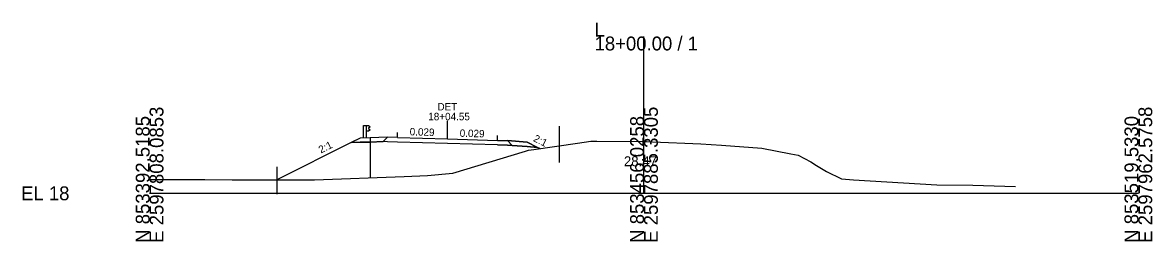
# Model space of a CAD drawing. Extents: x -26 to 1203, y -10 to 9526.
# Drawn here: x -25.7 to 202.8, y 7990.3 to 8034.4 of the extents above; entities that cross this region are included whole.
import ezdxf

# ---------------------------------------------------------------- set-up
doc = ezdxf.new("R2010")
doc.units = 0
for name, color, linetype in [('Exist Cross Section Cell', 7, 'Continuous'), ('Exist XS Center Line Elevation Label', 7, 'Continuous'), ('Exist XS Ground Line', 7, 'Continuous'), ('Prop XS Alignment Label', 7, 'Continuous'), ('Prop XS Earthwork Shape', 7, 'Continuous'), ('Prop XS EOT Tick Mark', 7, 'Continuous'), ('Prop XS Exc Vertical Line 1', 7, 'Continuous'), ('Prop XS Exc Vertical Line 2', 7, 'Continuous'), ('Prop XS Finish Grade', 7, 'Continuous'), ('Prop XS Finish Grade Earthwork', 7, 'Continuous'), ('Prop XS Finish Grade Paved Shoulder', 7, 'Continuous'), ('Prop XS Finish Grade Pavement', 7, 'Continuous'), ('Prop XS Guardrail', 7, 'Continuous'), ('Prop XS Pvmt Edge Slope', 7, 'Continuous'), ('Prop XS SE Text', 7, 'Continuous'), ('Prop XS Side Slope Text', 7, 'Continuous'), ('Prop XS Station Labels', 7, 'Continuous'), ('Prop XS Subgrade Earthwork', 7, 'Continuous'), ('Scratch_Level_1', 7, 'Continuous'), ('Scratch_Level_2', 7, 'Continuous')]:
    doc.layers.add(name, color=color, linetype=linetype)

msp = doc.modelspace()

# ---------------------------------------------------------------- linework, layer by layer
at = {"layer": 'Exist Cross Section Cell'}
for p, q in [((100, 8000), (100, 8031.63)), ((0, 8000), (100, 8000)), ((100, 8000), (200, 8000))]:
    msp.add_line(p, q, dxfattribs=at)
at = {"layer": 'Exist XS Ground Line'}
for p, q in [((77.75, 8008.84), (86.54, 8010.15)), ((86.54, 8010.15), (89.23, 8010.54)), ((89.23, 8010.54), (90.45, 8010.54)), ((90.45, 8010.54), (100, 8010.47)), ((100, 8010.47), (100.49, 8010.47)), ((100.49, 8010.47), (101.71, 8010.42)), ((101.71, 8010.42), (111.51, 8009.99)), ((61.31, 8004.06), (76.04, 8008.53)), ((76.04, 8008.53), (76.67, 8008.69)), ((76.67, 8008.69), (77.75, 8008.84)), ((111.51, 8009.99), (115.66, 8009.7)), ((115.66, 8009.7), (123.82, 8009.14)), ((123.82, 8009.14), (129.69, 8007.97)), ((129.69, 8007.97), (131.21, 8007.7)), ((131.21, 8007.7), (133.73, 8006.33)), ((133.73, 8006.33), (134.9, 8005.61)), ((134.9, 8005.61), (136.93, 8004.39)), ((33.33, 8002.71), (51.5, 8003.41)), ((51.5, 8003.41), (56.24, 8003.57)), ((56.24, 8003.57), (61.31, 8004.06)), ((136.93, 8004.39), (139.94, 8002.91)), ((0, 8002.82), (1.73, 8002.77)), ((1.73, 8002.77), (6.34, 8002.78)), ((6.34, 8002.78), (11.16, 8002.8)), ((11.16, 8002.8), (16.68, 8002.72)), ((16.68, 8002.72), (33.33, 8002.71)), ((139.94, 8002.91), (142.38, 8002.75)), ((142.38, 8002.75), (159.24, 8001.69)), ((159.24, 8001.69), (166.54, 8001.67)), ((166.54, 8001.67), (175.14, 8001.4))]:
    msp.add_line(p, q, dxfattribs=at)
at = {"layer": 'Prop XS Earthwork Shape'}
msp.add_lwpolyline([(60.25, 8010.06), (50.14, 8010.35), (48.14, 8010.41), (47.24, 8010.43), (44.59, 8010.35), (42.59, 8010.29), (40.75, 8010.23), (25.71, 8002.71), (33.33, 8002.71), (51.5, 8003.41), (56.24, 8003.57), (61.31, 8004.06), (76.04, 8008.53), (76.67, 8008.69), (77.75, 8008.84), (78.94, 8009.02), (78.44, 8009.27), (76.37, 8009.44), (73.31, 8009.68), (72.37, 8009.71), (70.37, 8009.77)], close=True, dxfattribs=at)
at = {"layer": 'Prop XS EOT Tick Mark'}
for p, q in [((50.14, 8011.27), (50.14, 8012.27)), ((70.37, 8010.68), (70.37, 8011.68))]:
    msp.add_line(p, q, dxfattribs=at)
at = {"layer": 'Prop XS Exc Vertical Line 1'}
msp.add_line((25.7, 8005.37), (25.7, 7999.8), dxfattribs=at)
at = {"layer": 'Prop XS Exc Vertical Line 2'}
msp.add_line((82.82, 8013.56), (82.82, 8006.22), dxfattribs=at)
at = {"layer": 'Prop XS Finish Grade'}
for p, q in [((42.59, 8011.15), (40.75, 8010.23)), ((44.59, 8011.21), (42.59, 8011.15)), ((48.14, 8011.32), (44.59, 8011.21)), ((72.37, 8010.63), (76.37, 8010.31)), ((76.37, 8010.31), (78.44, 8009.27))]:
    msp.add_line(p, q, dxfattribs=at)
at = {"layer": 'Prop XS Finish Grade Earthwork'}
for p, q in [((40.75, 8010.23), (25.71, 8002.71)), ((78.44, 8009.27), (78.94, 8009.02))]:
    msp.add_line(p, q, dxfattribs=at)
at = {"layer": 'Prop XS Finish Grade Paved Shoulder'}
for p, q in [((50.14, 8011.27), (48.14, 8011.32)), ((70.37, 8010.68), (72.37, 8010.63))]:
    msp.add_line(p, q, dxfattribs=at)
at = {"layer": 'Prop XS Finish Grade Pavement'}
for p, q in [((50.14, 8011.27), (60.25, 8010.98)), ((60.25, 8010.98), (70.37, 8010.68))]:
    msp.add_line(p, q, dxfattribs=at)
at = {"layer": 'Prop XS Guardrail'}
for p, q in [((43.27, 8013.67), (43.77, 8013.67)), ((43.27, 8011.17), (43.27, 8013.67)), ((43.77, 8013.67), (44.27, 8013.67)), ((43.77, 8013.67), (43.77, 8011.17)), ((44.27, 8012.54), (43.77, 8012.54)), ((44.27, 8013.67), (44.56, 8013.47)), ((44.56, 8013.35), (44.27, 8013.15)), ((44.27, 8013.15), (44.27, 8013.06)), ((44.27, 8013.06), (44.56, 8012.86)), ((44.56, 8012.74), (44.27, 8012.54)), ((44.56, 8013.47), (44.59, 8013.41)), ((44.59, 8013.41), (44.56, 8013.35)), ((44.56, 8012.86), (44.59, 8012.8)), ((44.59, 8012.8), (44.56, 8012.74))]:
    msp.add_line(p, q, dxfattribs=at)
at = {"layer": 'Prop XS Pvmt Edge Slope'}
for p, q in [((48.14, 8011.32), (47.24, 8010.43)), ((72.37, 8010.63), (73.31, 8009.68))]:
    msp.add_line(p, q, dxfattribs=at)
at = {"layer": 'Prop XS Side Slope Text'}
msp.add_line((60.25, 8010.98), (60.25, 8014.63), dxfattribs=at)
at = {"layer": 'Prop XS Subgrade Earthwork'}
for p, q in [((42.59, 8010.29), (40.75, 8010.23)), ((44.59, 8010.35), (42.59, 8010.29)), ((47.24, 8010.43), (44.59, 8010.35)), ((48.14, 8010.41), (47.24, 8010.43)), ((50.14, 8010.35), (48.14, 8010.41)), ((60.25, 8010.06), (50.14, 8010.35)), ((70.37, 8009.77), (60.25, 8010.06)), ((70.37, 8009.77), (72.37, 8009.71)), ((72.37, 8009.71), (73.31, 8009.68)), ((73.31, 8009.68), (76.37, 8009.44)), ((76.37, 8009.44), (78.44, 8009.27))]:
    msp.add_line(p, q, dxfattribs=at)
at = {"layer": 'Scratch_Level_1'}
for points in [[(42.59, 8011.15), (40.75, 8010.23), (42.59, 8010.29), (44.59, 8010.35), (47.24, 8010.43), (48.14, 8011.32), (44.59, 8011.21)], [(48.14, 8011.32), (44.59, 8011.21), (42.59, 8011.15), (40.75, 8010.23), (42.59, 8010.29), (44.59, 8010.35), (47.24, 8010.43)], [(76.37, 8009.44), (78.44, 8009.27), (76.37, 8010.31), (72.37, 8010.63), (73.31, 8009.68)]]:
    msp.add_lwpolyline(points, close=True, dxfattribs=at)
at = {"layer": 'Scratch_Level_2'}
msp.add_line((44.58, 8011.14), (44.58, 8003.14), dxfattribs=at)
msp.add_line((44.58, 8011.14), (44.58, 8003.14), dxfattribs=at)

# ---------------------------------------------------------------- texts
at = {"layer": 'Exist Cross Section Cell'}
for s, p in [('L', (90, 8031.63)), ('18+00.00 / 1', (90, 8028.83)), ('EL 18', (-26, 7998.6))]:
    msp.add_text(s, height=2.8, dxfattribs=at).set_placement(p)
for s, p in [('E 2597808.0853', (2.8, 7990)), ('E 2597885.3305', (102.8, 7990)), ('E 2597962.5758', (202.8, 7990)), ('N 853392.5185', (0, 7990)), ('N 853456.0258', (100, 7990)), ('N 853519.5330', (200, 7990))]:
    msp.add_text(s, height=2.8, rotation=90, dxfattribs=at).set_placement(p)
at = {"layer": 'Exist XS Center Line Elevation Label'}
msp.add_text('28.47', height=2, dxfattribs=at).set_placement((95.93, 8005.47))
at = {"layer": 'Prop XS Alignment Label'}
msp.add_text('DET', height=1.5, dxfattribs=at).set_placement((58.22, 8016.72))
at = {"layer": 'Prop XS SE Text'}
for rotation, p in [(358.3515, (52.59, 8011.7)), (358.3535, (62.71, 8011.41))]:
    msp.add_text('0.029', height=1.5, rotation=rotation, dxfattribs=at).set_placement(p)
at = {"layer": 'Prop XS Side Slope Text'}
for rotation, p in [(26.5651, (34.64, 8008.01)), (333.4349, (77.48, 8010.58))]:
    msp.add_text('2:1', height=1.5, rotation=rotation, dxfattribs=at).set_placement(p)
at = {"layer": 'Prop XS Station Labels'}
msp.add_text('18+04.55', height=1.5, dxfattribs=at).set_placement((56.36, 8014.74))

doc.saveas('drawing.dxf')
